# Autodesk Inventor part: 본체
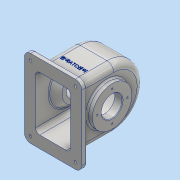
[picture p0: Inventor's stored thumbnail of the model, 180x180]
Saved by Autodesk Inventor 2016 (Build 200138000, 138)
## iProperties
Created: 2018-11
Part Number: 본체
Material: 알루미늄 6061
Document SubType Name: Modeling
Designer: 공506_41
Density: 2.7 g/cm^3
Appearance: 알루미늄 - 평지
Mass: 1091.96 g
Surface Area: 1182.19 cm^2
Volume: 404.431 cm^3
Author: 공506_41
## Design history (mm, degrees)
sketch "스케치1"
  geometry: L1 (-55, 75)-(55, 75); L2 (55, 75)-(55, -75); L3 (55, -75)-(-55, -75); L4 (-55, -75)-(-55, 75); L5 (-55, 75)-(55, -75); L6 (55, 75)-(-55, -75); 1 further point
  constraints: 12 end point, 2 midpoint, 2 parallel, 1 horizontal, 1 perpendicular
  dimensions: "d0" = 110 distance of L2.end L3.end; "d1" = 150 distance of L1.end L2.end
extrude "돌출1" new body sketch "스케치1" distance "d2" = 10; taper "d3" = 0 deg
sketch "스케치5"
  geometry: L1 (-38.5, -58)-(38.5, -58); L2 (38.5, -58)-(38.5, 58); L3 (38.5, 58)-(-38.5, 58); L4 (-38.5, 58)-(-38.5, -58); L5 (-38.5, -58)-(38.5, 58); L6 (38.5, -58)-(-38.5, 58); 1 further point
  constraints: 12 end point, 2 midpoint, 2 parallel, 1 horizontal, 1 perpendicular
  dimensions: "d6" = 77 distance of L3.end L2.end; "d7" = 116 distance of L2.end L1.end
extrude "돌출2" join sketch "스케치5" distance "d8" = 126; taper "d9" = 0 deg
sketch "스케치7"
  geometry: L1 (133, -10)-(-17, -10) reference; C1 r 38 at (58, 55); 2 further points
  constraints: 1 centre point, 1 midpoint, 1 vertical alignment
  dimensions: "d10" = 76 diameter of C1; "d11" = 65 distance from line of C1.centre L1
extrude "돌출3" join sketch "스케치7" distance "d12" = 5; taper "d13" = 0 deg
sketch "스케치8"
  geometry: C1 r 20 at (0, 0); 1 further point
  constraints: 1 centre point
  dimensions: "d14" = 40 diameter of C1
extrude "돌출4" cut sketch "스케치8" distance "d15" = 24; taper "d16" = 0 deg
sketch "스케치9"
  geometry: L1 (133, -10)-(-17, -10) reference; C1 r 38 at (58, 55); 2 further points
  constraints: 1 centre point, 1 midpoint, 1 vertical alignment
  dimensions: "d17" = 76 diameter of C1; "d18" = 65 distance from line of L1 C1.centre
extrude "돌출5" join sketch "스케치9" distance "d19" = 10; taper "d20" = 0 deg
sketch "스케치10"
  geometry: C1 r 20 at (0, 0); C2 r 38 at (0, 0) reference; 1 further point
  constraints: 1 centre point, 1 concentric
  dimensions: "d21" = 40 diameter of C1
extrude "돌출6" cut sketch "스케치10" distance "d22" = 100; taper "d23" = 0 deg
fillet "모깎기1" dims "d24" = 58
sketch "스케치11"
  geometry: L1 (10, 58)-(78, 58) reference; L2 (10, -58)-(78, -58) reference; L3 (0, 52)-(78, 52); L4 (78, -52)-(0, -52); L5 (0, 75)-(0, -75) reference; L6 (0, 52)-(0, -52); A1 r 58 centre (78, 0) between (78, -58) and (78, 58) reference; A2 r 52 centre (78, 0) between (78, -52) and (78, 52); 1 further point
  constraints: 6 end point, 2 horizontal, 2 point on circle, 2 point on line, 2 tangent, 1 centre point, 1 vertical
  dimensions: "d25" = 6 radial gap between concentric circles of A1 A2
extrude "돌출7" cut sketch "스케치11" stored distance "d26" = 67; taper "d27" = 0 deg
node "작업 평면1"
sketch "스케치14"
  geometry: C1 r 28 at (0, 0); C2 r 20 at (0, 0) reference; 1 further point
  constraints: 1 centre point, 1 concentric
  dimensions: "d52" = 56 diameter of C1
extrude "돌출8" join sketch "스케치14" distance "d53" = 14; taper "d54" = 40 deg
sketch "스케치15"
  geometry: C1 r 20 at (0, 0) reference; 1 further point
extrude "돌출9" cut sketch "스케치15" stored distance "d55" = 14; taper "d56" = 0 deg
sketch "스케치16"
  geometry: L1 (-55, 75)-(-55, -75) reference; L2 (-55, -75)-(55, -75) reference; C1 r 6 at (-43, -63); 1 further point
  constraints: 1 centre point
  dimensions: "d57" = 12 diameter of C1; "d58" = 12 distance from line of C1.centre L1; "d59" = 12 distance from line of C1.centre L2
extrude "돌출10" cut sketch "스케치16" distance "d60" = 4; taper "d61" = 0 deg
sketch "스케치17"
  geometry: C1 r 6 at (0, 0) reference; C2 r 2.5 at (0, 0); 1 further point
  constraints: 1 centre point, 1 coincident
  dimensions: "d62" = 5 diameter of C2
extrude "돌출11" cut sketch "스케치17" stored distance "d63" = 4; taper "d64" = 0 deg
node "작업 평면2"
sketch "스케치18"
  geometry: C1 r 6 at (0, 0); 1 further point
  constraints: 1 centre point, 1 coincident
  dimensions: "d72" = 12 diameter of C1
extrude "돌출12" join sketch "스케치18" stored distance "d73" = 4; taper "d74" = 5 deg
sketch "스케치19"
  geometry: 2 further points
  constraints: 1 coincident
hole "구멍3" sketch "스케치19" at (0, 0) diameter "d75" = 4.459; stored, may be unused: countersink angle "d79" = 90 deg, drill point angle "d81" = 118 deg; dims "d76" = 20, "d77" = 4, "d78" = 2, "d80" = 20
sketch "스케치20"
  geometry: L1 (93.5, -10)-(-16.5, -10) reference; L2 (0, 0)-(0, 68) reference; 2 further points
  constraints: 1 other
  dimensions: "d82" = 40 distance from line of L1 point (38.5, 30); "d83" = 38.5 distance from line of point (38.5, 30) L2
feature "엠보싱1" sketch "스케치20" dims "d84" = 0.5, "d85" = 0
fillet "모깎기2" dims "d86" = 12
fillet "모깎기3" dims "d87" = 3
fillet "모깎기4" dims "d88" = 13
fillet "모깎기5" dims "d89" = 3
fillet "모깎기6" dims "d90" = 3
fillet "모깎기7" dims "d91" = 3
fillet "모깎기8" dims "d92" = 3
chamfer "모따기1" distance "d93" = 1; stored, may be unused: second distance "d94" = 2, angle "d95" = 45 deg
chamfer "모따기2" distance "d96" = 1; stored, may be unused: second distance "d97" = 2, angle "d98" = 45 deg
fillet "모깎기9" dims "d99" = 8
fillet "모깎기10" dims "d100" = 3
sketch "스케치21"
  geometry: C1 r 21 at (0, 0) reference; 2 further points
  constraints: 1 horizontal alignment
  dimensions: "d101" = 29 distance of C1.centre point (29, 0)
hole "구멍4" sketch "스케치21" at (29, 0) diameter "d102" = 3.242; stored, may be unused: countersink angle "d106" = 90 deg, drill point angle "d108" = 118 deg; dims "d103" = 8, "d104" = 4, "d105" = 2, "d107" = 10
sketch "스케치22"
  geometry: C1 r 21 at (0, 0) reference; 2 further points
  constraints: 1 vertical alignment
  dimensions: "d112" = 29 distance of C1.centre point (0, 29)
hole "구멍5" sketch "스케치22" at (0, 29) diameter "d113" = 3.242; stored, may be unused: countersink angle "d117" = 90 deg, drill point angle "d119" = 118 deg; dims "d114" = 8, "d115" = 4, "d116" = 2, "d118" = 10
node "솔리드1"
pattern_linear "직사각형 패턴1" dims "d67" = 126, "d70" = 86
pattern_circular "원형 패턴3" dims angle "d110" = 360 deg
pattern_circular "원형 패턴4" dims angle "d121" = 360 deg
other parameters: "d51" = -24, "d71" = 142
